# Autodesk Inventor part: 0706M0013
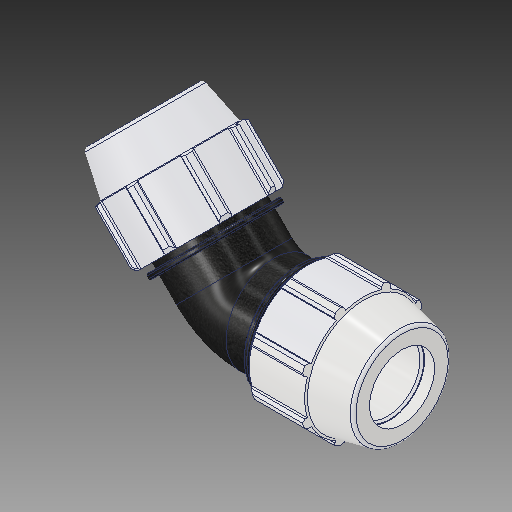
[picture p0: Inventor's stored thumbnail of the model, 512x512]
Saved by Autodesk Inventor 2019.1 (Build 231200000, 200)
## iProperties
Created: 2017-02
Part Number: 0706M0013
Material: PVC-Piping
Description: PLASSON 45° ELBOW 1 1/4'' - 1 1/4''
Document SubType Name: Modeling
Designer: KIM
Mass: 92.6774 g
Surface Area: 199.44 cm^2
Volume: 66.1981 cm^3
Density: 1.4 g/cm^3
Appearance: PTFE
Author: KIM
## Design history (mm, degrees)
derived "0706M0.ipt"
feature "Solid1::0706M0.ipt"
tag "TaggingFeature1"
body "Solid1"
other parameters: "d2" = 42.1, "d4" = 8.17033, "d5" = 24.511, "d7" = 82.042, "d9" = 14.00629, "d11" = 3.26813, "d13" = 120 deg, "d14" = 63.15, "d15" = 12 deg, "d16" = 71.37654, "d18" = 2.105, "d19" = 35 deg, "d20" = 17.5 deg, "d21" = 76.29906, "d23" = 0, "d25" = 360 deg, "d27" = 1.64084, "d33" = 0.842, "d42" = 36.27628, "d43" = 2.46126, "d46" = 1.263, "d51" = 98.044, "d59" = 135 deg, "d63" = 83.058, "d67" = 61.5315, "d68" = 3.26813, "d72" = 1.5, "d73" = 0, "d74" = 0, "d_" = 42.1, "E_" = 82.042, "A_" = 98.044, "l_" = 83.058
